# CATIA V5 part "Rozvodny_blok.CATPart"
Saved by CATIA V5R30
Part number: Rozvodny_blok
Definition: EH 61001 IMT2_278_37 __ A=90
Nomenclature: EH 61001 IMT2_278_37 __ A=90
Source: Unknown
Description: PART--DESC
Bounding box of the stored display mesh (mm): x -139 to 139, y -28 to 173, z 35.95 to 93.45
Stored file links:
  E:\Bakalarka\Model\Forma_v7\Rozvodny_blok.CATPart
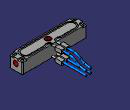
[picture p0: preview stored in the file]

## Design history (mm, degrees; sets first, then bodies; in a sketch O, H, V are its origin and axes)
Body1 "MANIFOLD_SOLID_BREP #3762" (main body)
  Solid1: solid without history
  DatumSurface1
  Sketch1 on face of Solid1, origin (0, 75, 0), H (-1, 0, 0), V (0, 0, 1)
    circle A1 centre (10, 43.45) radius 4
    point P1 (10, 43.45)
    circle A2 centre (-9, 43.45) radius 4
    point P2 (-9, 43.45)
    reference projected line E1 (-17.5, 50.95) -> (-2.5, 50.95) from edge [face of Solid1 | face of Solid1]
    reference projected line E2 (-17.5, 50.95) -> (-17.5, 35.95) from edge [face of Solid1 | face of Solid1]
    reference projected line E3 (-2.5, 35.95) -> (-17.5, 35.95) from edge [face of Solid1 | face of Solid1]
    reference projected line E4 (-2.5, 50.95) -> (-2.5, 35.95) from edge [face of Solid1 | face of Solid1]
    reference projected line E5 (2.5, 50.95) -> (2.5, 35.95) from edge [face of Solid1 | face of Solid1]
    reference projected line E6 (2.5, 50.95) -> (17.5, 50.95) from edge [face of Solid1 | face of Solid1]
    radius A2 = 4
    radius A1 = 4
    distance P2 E1 = 7.5
    distance P2 E2 = 8.5
    distance P2 E3 = 7.5 (reference)
    distance P2 E4 = 6.5 (reference)
    distance P1 E5 = 7.5
    distance E6 P1 = 7.5
  Pad1: profile Sketch1, direction (0, 1, 0), up to face of DatumSurface1
  Plane1: type Offset, RefPlane face of Solid1, Offset 7.5
  DatumCurve1
  DatumCurve2
  Sketch2 on Plane1, origin (10, 0, 0), H (0, -1, 0), V (0, 0, 1)
    point P1 (-75, 85.95)
    line L1 (-75, 85.95) -> (-102.9946, 85.95)
    arc A1 centre (-102.9946, 41.9394) radius 44.0106 from (-102.9946, 85.95) to (-131.4212, 75.5379) ccw
    arc A2 centre (-157.6356, 106.5218) radius 40.5857 from (-131.4212, 75.5379) to (-149.0962, 66.8446) cw
    line L2 (-149.0962, 66.8446) -> (-173, 61.7)
    point P7 (-173, 61.7)
    reference projected line E1 (-173, 96.7) -> (-173, 0) from edge of DatumCurve1
    reference projected line E2 (-173, 96.7) -> (173, 96.7) from edge of DatumCurve2
    reference projected line E3 (-75, 93.45) -> (-75, 78.45) from edge [face of Solid1 | face of Solid1]
    reference projected line E4 (-75, 93.45) -> (-48, 93.45) from edge [face of Solid1 | face of Solid1]
    distance P7 E1 = 0
    distance P7 E2 = 35
    length L2 = 24.4511
    radius A2 = 40.5857
    radius A1 = 44.0106
    length L1 = 27.9946
    distance P1 E3 = 0
    distance P1 E4 = 7.5
    horizontal: L1 H
    tangency: A1 L1, A2 A1, L2 A2
  Plane2: type Offset, RefPlane face of Solid1, Offset 7.5
  DatumSurface2
  Sketch3 on face of Solid1, origin (0, 75, 0), H (-1, 0, 0), V (0, 0, 1)
    circle A1 centre (10, 85.95) radius 4
    point P1 (10, 85.95)
    reference projected line E1 (2.5, 93.45) -> (17.5, 93.45) from edge [face of Solid1 | face of Solid1]
    reference projected line E2 (2.5, 93.45) -> (2.5, 78.45) from edge [face of Solid1 | face of Solid1]
    radius A1 = 4
    distance P1 E1 = 7.5
    distance P1 E2 = 7.5
  Sketch4 on Plane2, origin (-10, 0, 0), H (0, -1, 0), V (0, 0, 1)
    projected line E1 (-75, 85.95) -> (-102.9946, 85.95) from Sketch2.L1
    projected line E2 (-149.0962, 66.8446) -> (-173, 61.7) from Sketch2.L2
    projected arc E3 centre (-102.9946, 41.9394) radius 44.0106 from (-102.9946, 85.95) to (-131.4212, 75.5379) ccw from Sketch2.A1
    projected arc E4 centre (-157.6356, 106.5218) radius 40.5857 from (-149.0962, 66.8446) to (-131.4212, 75.5379) ccw from Sketch2.A2
  Rib1: profile Sketch3, centre curve Sketch4
  DatumSurface3
  Sketch5 on face of Solid1, origin (0, 75, 0), H (-1, 0, 0), V (0, 0, 1)
    circle A1 centre (-10, 85.95) radius 4
    point P1 (-10, 85.95)
    reference projected line E1 (-17.5, 93.45) -> (-2.5, 93.45) from edge [face of Solid1 | face of Solid1]
    reference projected line E2 (-2.5, 93.45) -> (-2.5, 78.45) from edge [face of Solid1 | face of Solid1]
    radius A1 = 4
    distance P1 E1 = 7.5
    distance P1 E2 = 7.5
  Rib2: profile Sketch5, centre curve Sketch2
